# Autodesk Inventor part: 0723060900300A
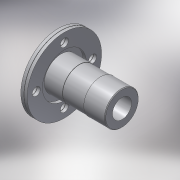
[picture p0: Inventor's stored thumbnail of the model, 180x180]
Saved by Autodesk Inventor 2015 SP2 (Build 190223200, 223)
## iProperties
Created: 2017-02
Part Number: 0723060900300A
Material: PVC-Piping
Description: PLASSON FLANGE ADAPTOR WITH METAL FLANGE 90-3"
Document SubType Name: Modeling
Designer: KIM
Mass: 92.6774 g
Surface Area: 199.44 cm^2
Volume: 66.1981 cm^3
Density: 1.4 g/cm^3
Appearance: Smooth - White
Author: Кирилл
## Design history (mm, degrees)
derived "872306.ipt"
feature "Solid1::872306.ipt"
tag "TaggingFeature1"
body "Solid1"
other parameters: "d73" = 17.5, "d74" = 90 deg, "d75" = 0.3, "d77" = 18, "d80" = 0, "d82" = 360 deg, "d96" = 0.3, "d99" = 360 deg, "d103" = 175, "d104" = 1.8, "d107" = 117, "d108" = 4.375, "d116" = 88.2, "d117" = 58.33333, "d118" = 58.33333, "d120" = 4.5, "H_" = 175, "S_" = 18
